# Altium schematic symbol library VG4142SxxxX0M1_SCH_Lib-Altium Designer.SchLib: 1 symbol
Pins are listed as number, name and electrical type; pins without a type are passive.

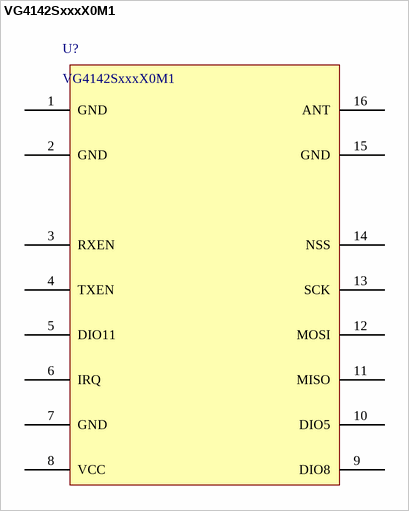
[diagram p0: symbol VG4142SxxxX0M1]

## VG4142SxxxX0M1
designator U?
pins: 1 GND, 2 GND, 3 RXEN, 4 TXEN, 5 DIO11, 6 IRQ, 7 GND, 8 VCC, 9 DIO8, 10 DIO5, 11 MISO, 12 MOSI, 13 SCK, 14 NSS, 15 GND, 16 ANT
